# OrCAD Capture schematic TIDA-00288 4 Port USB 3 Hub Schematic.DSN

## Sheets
1 PAGE1_BLOCK_DIAGRAM: title: BLOCK DIAGRAM; rev: B
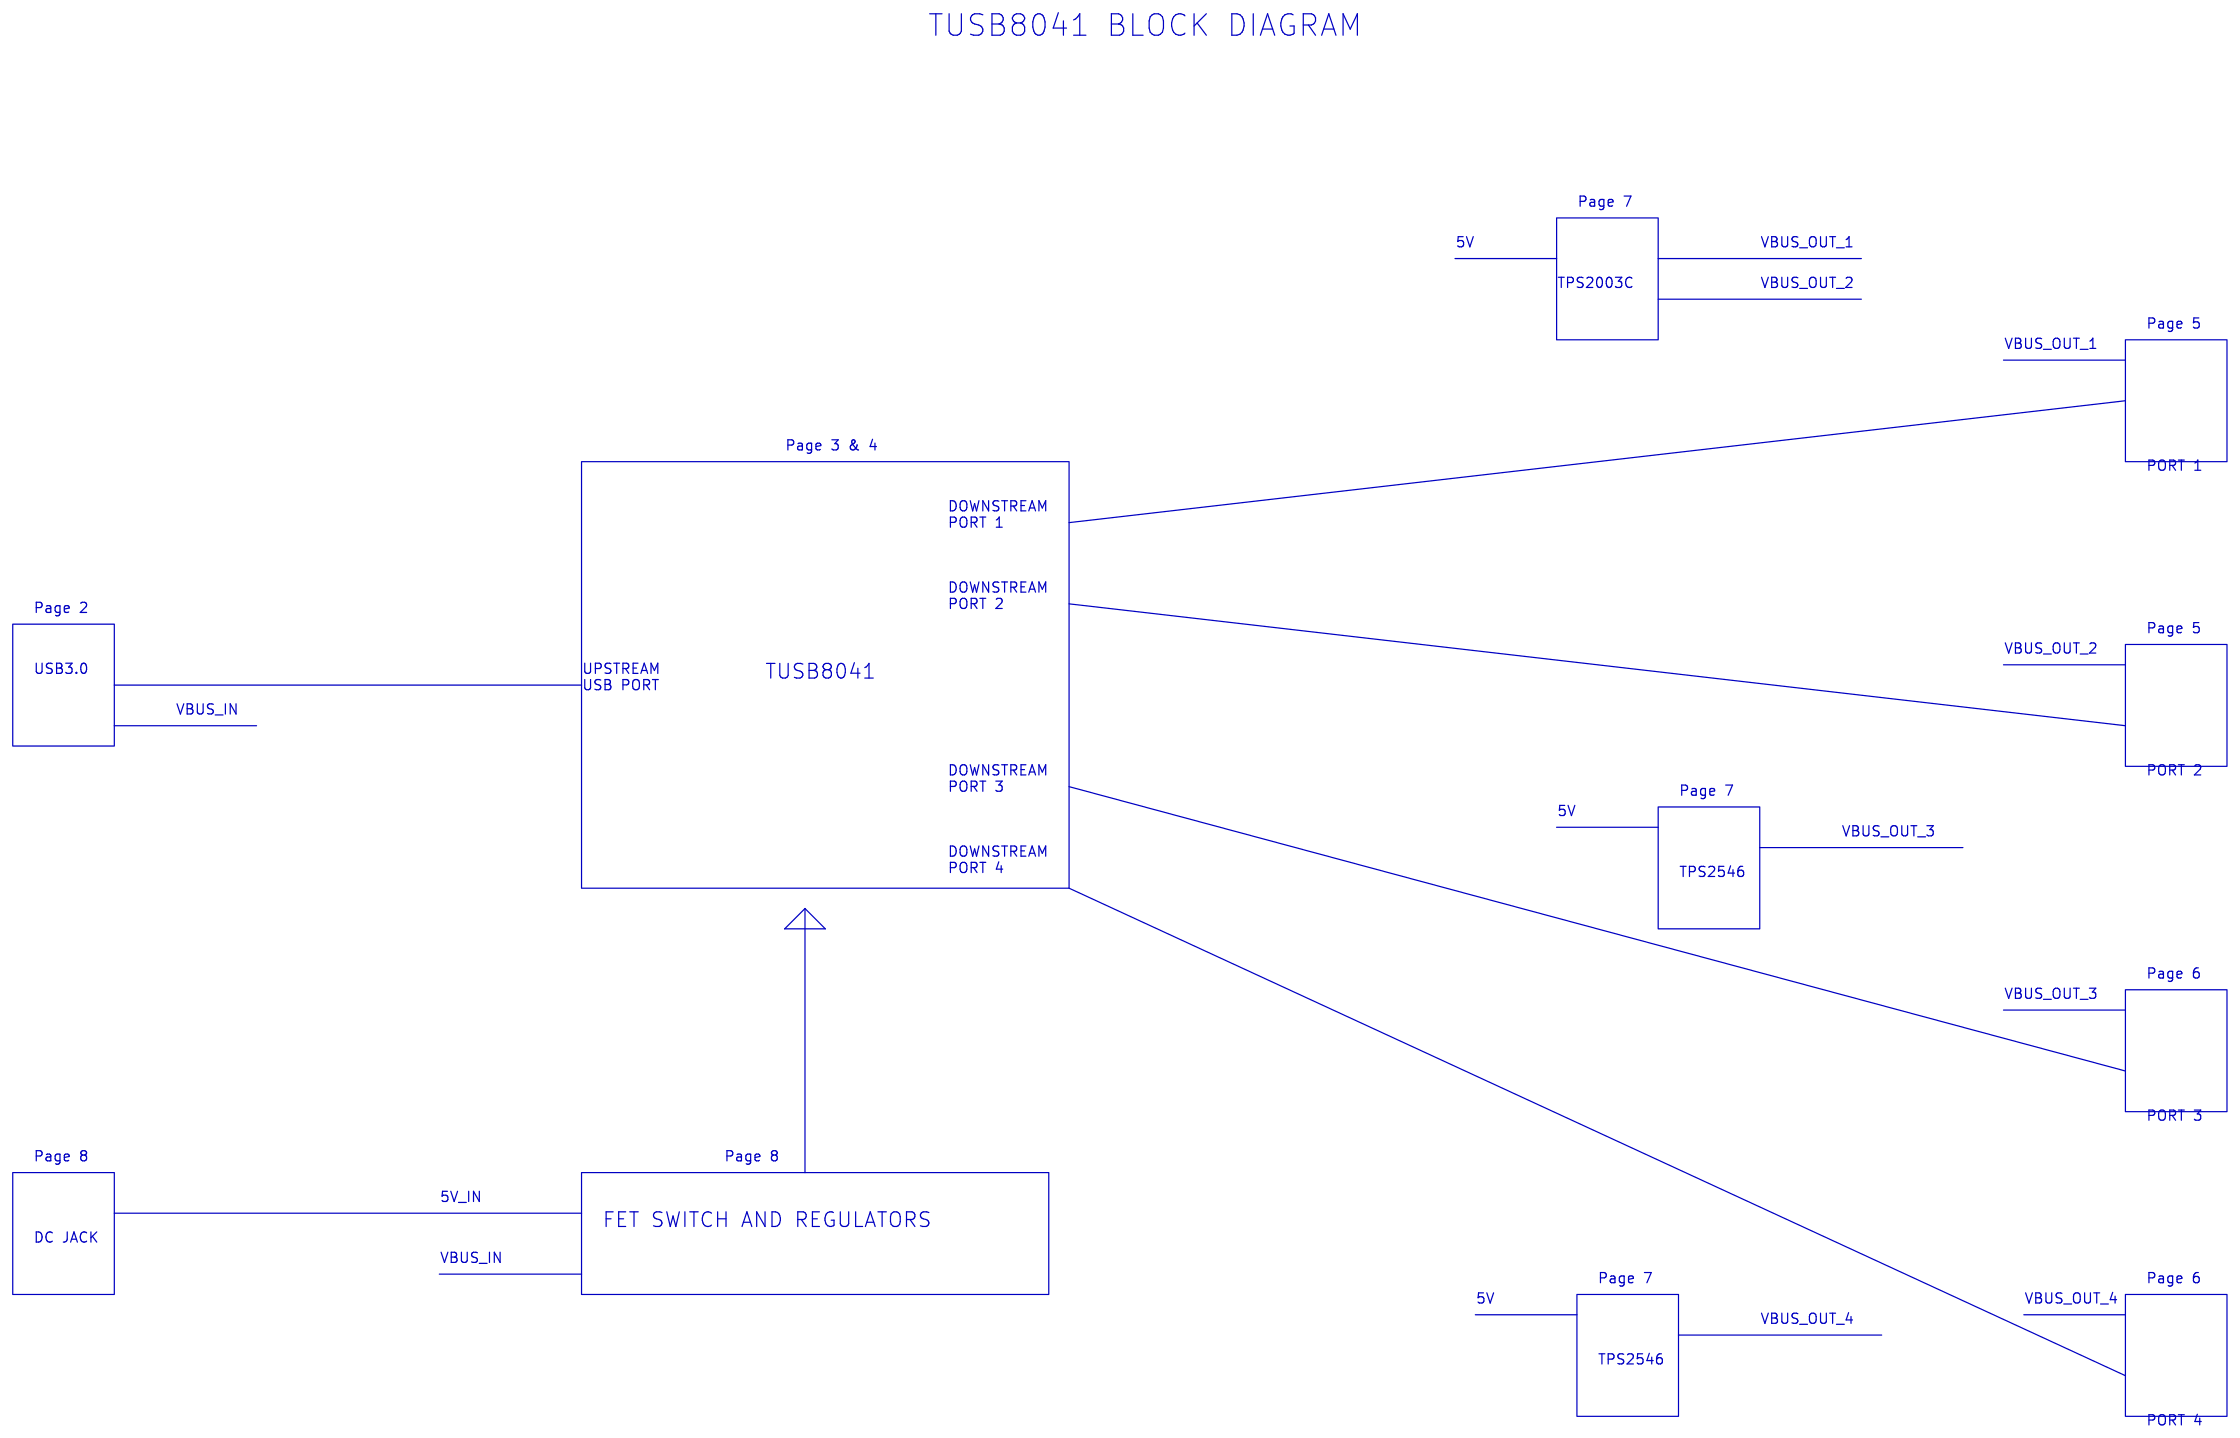
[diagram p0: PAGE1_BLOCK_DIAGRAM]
2 PAGE2_USB3_MICRO_B: size B; title: USB 3.0 MICRO-B CONNECTOR
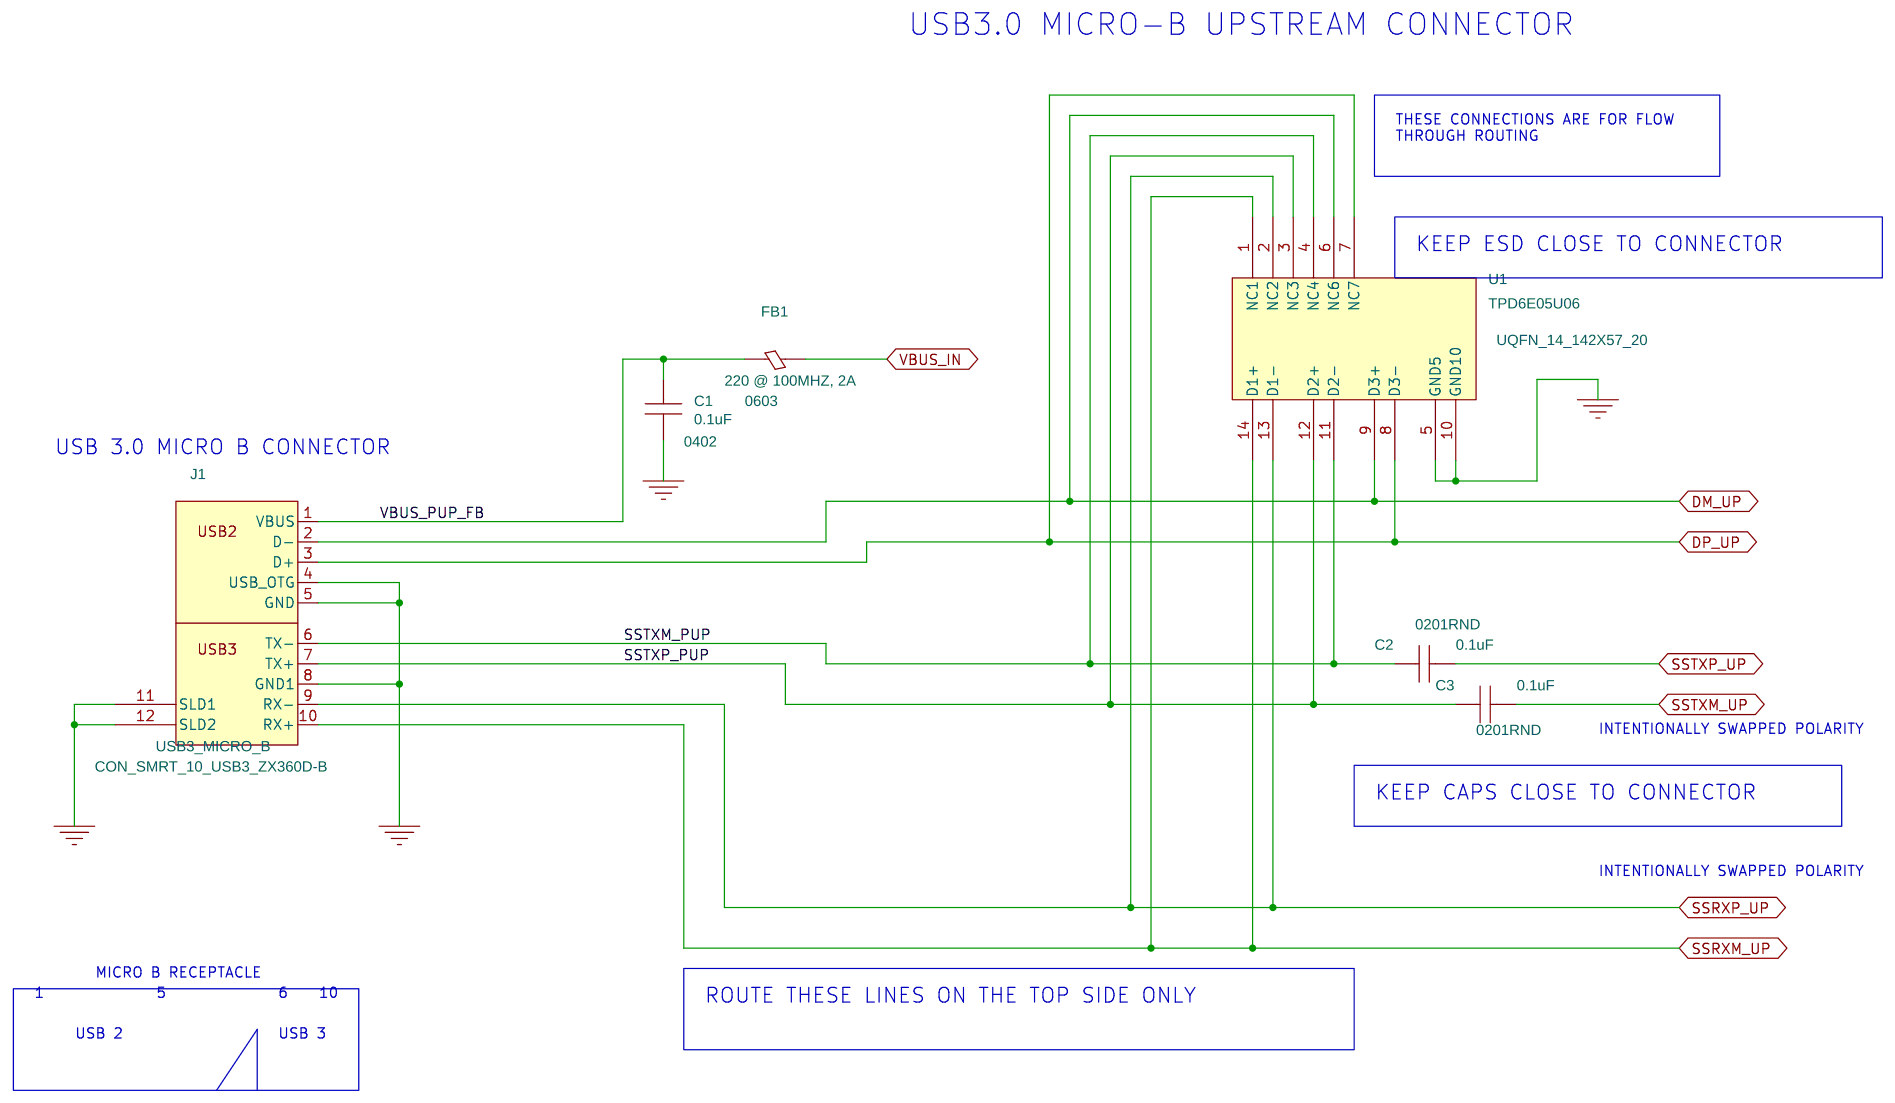
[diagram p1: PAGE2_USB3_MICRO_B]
3 PAGE3_TUSB8041: size B; title: TUSB8041 - PAGE 1
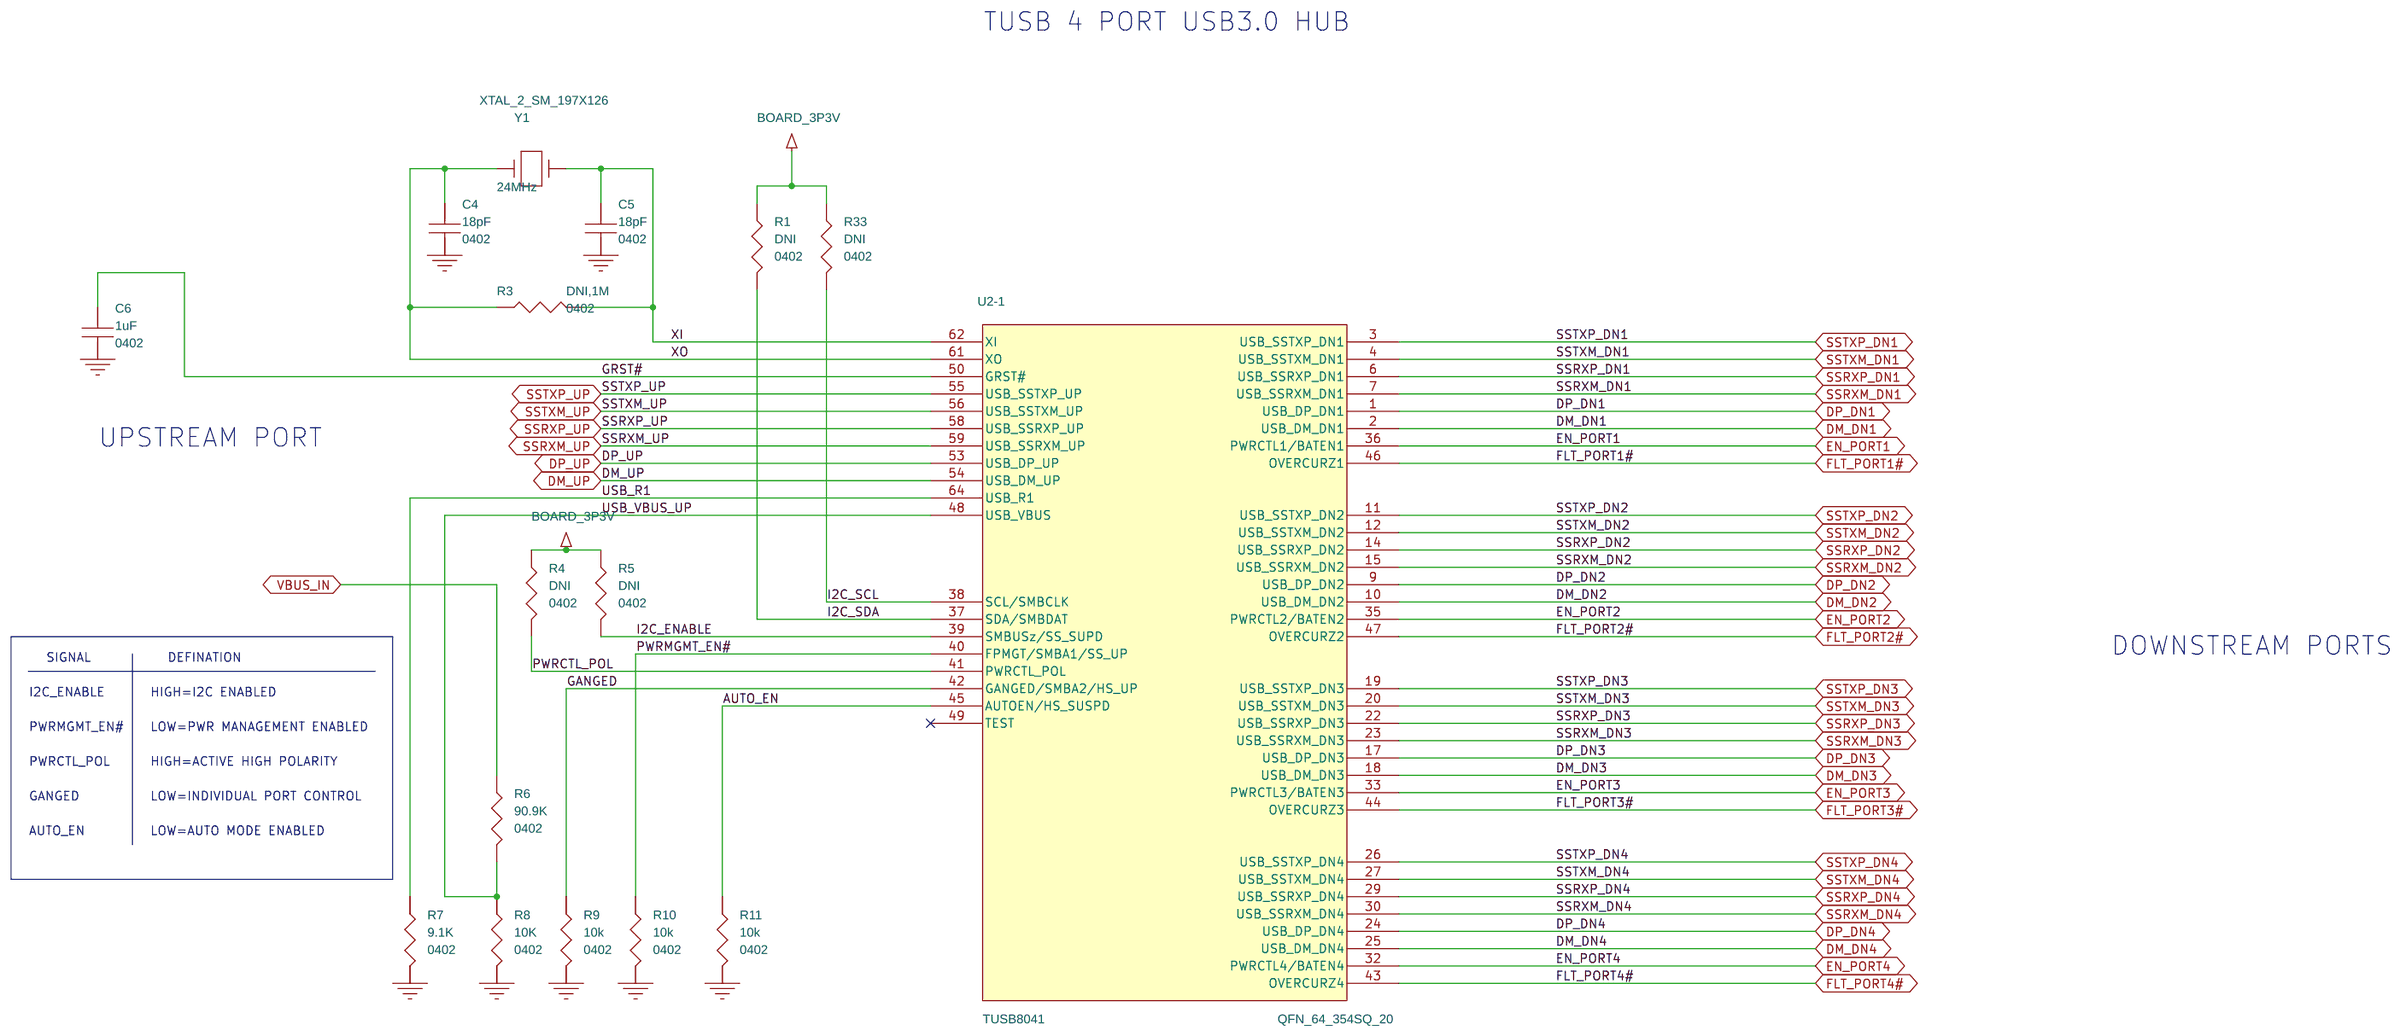
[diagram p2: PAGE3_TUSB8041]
4 PAGE4_TUSB8041_POWER: size B; title: TUSB POWER FOR HUB
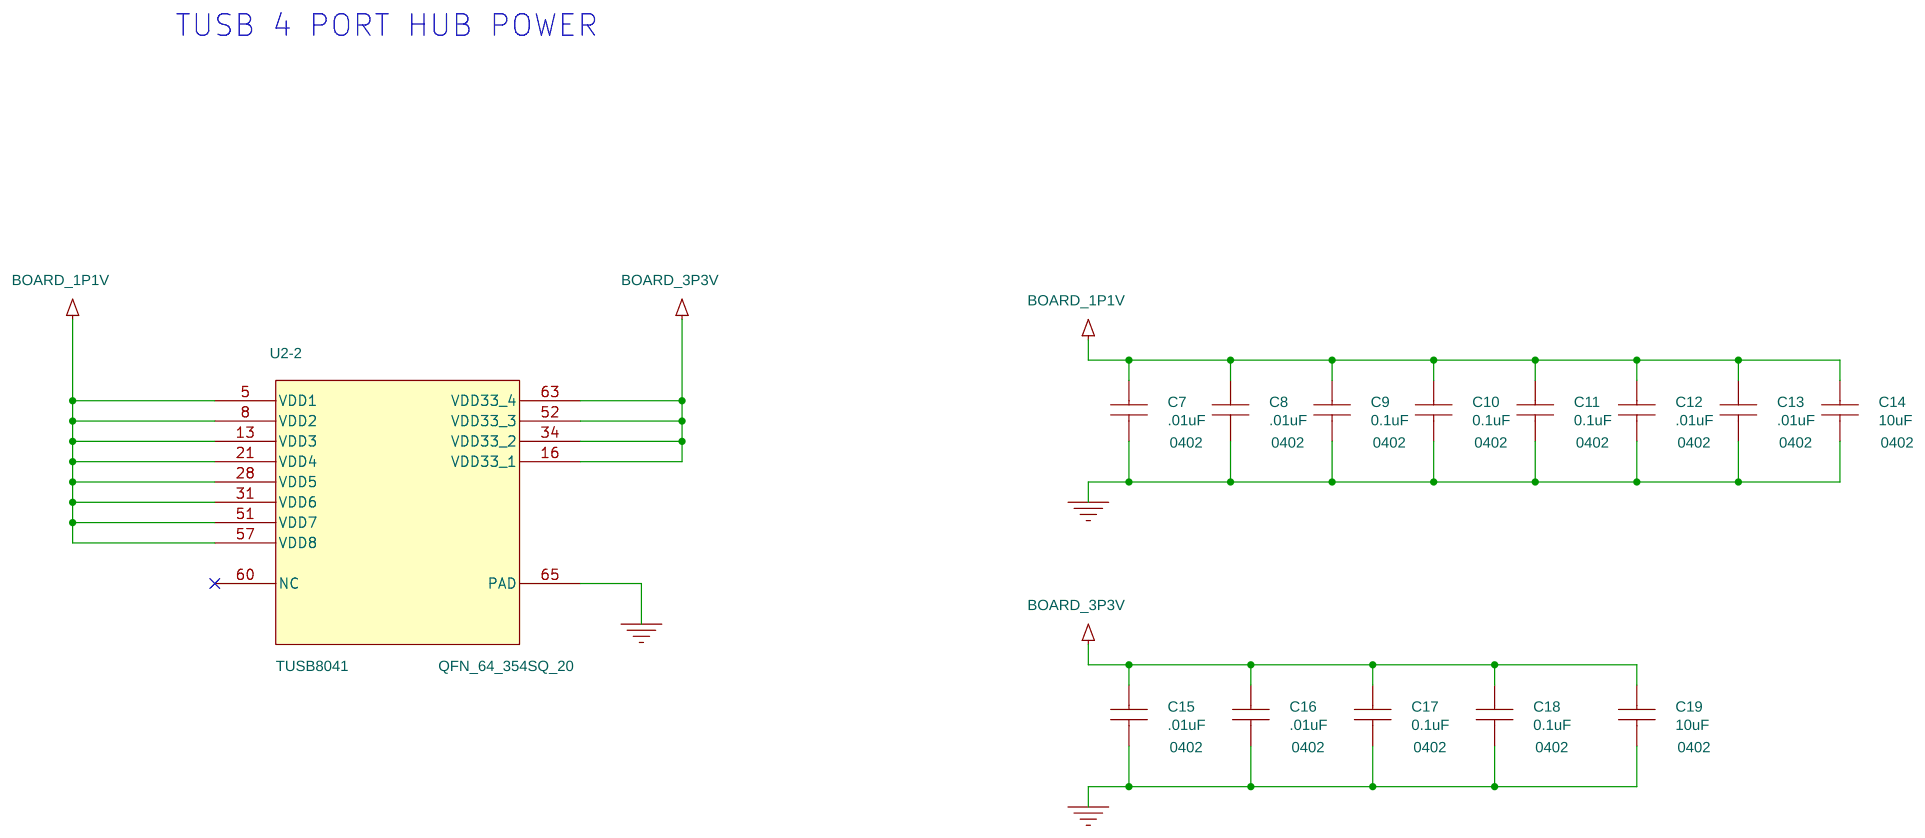
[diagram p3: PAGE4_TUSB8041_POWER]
5 PAGE5_USB_PORTS_1_2: size B; title: USB DOWNSTREAM PORTS 1 & 2
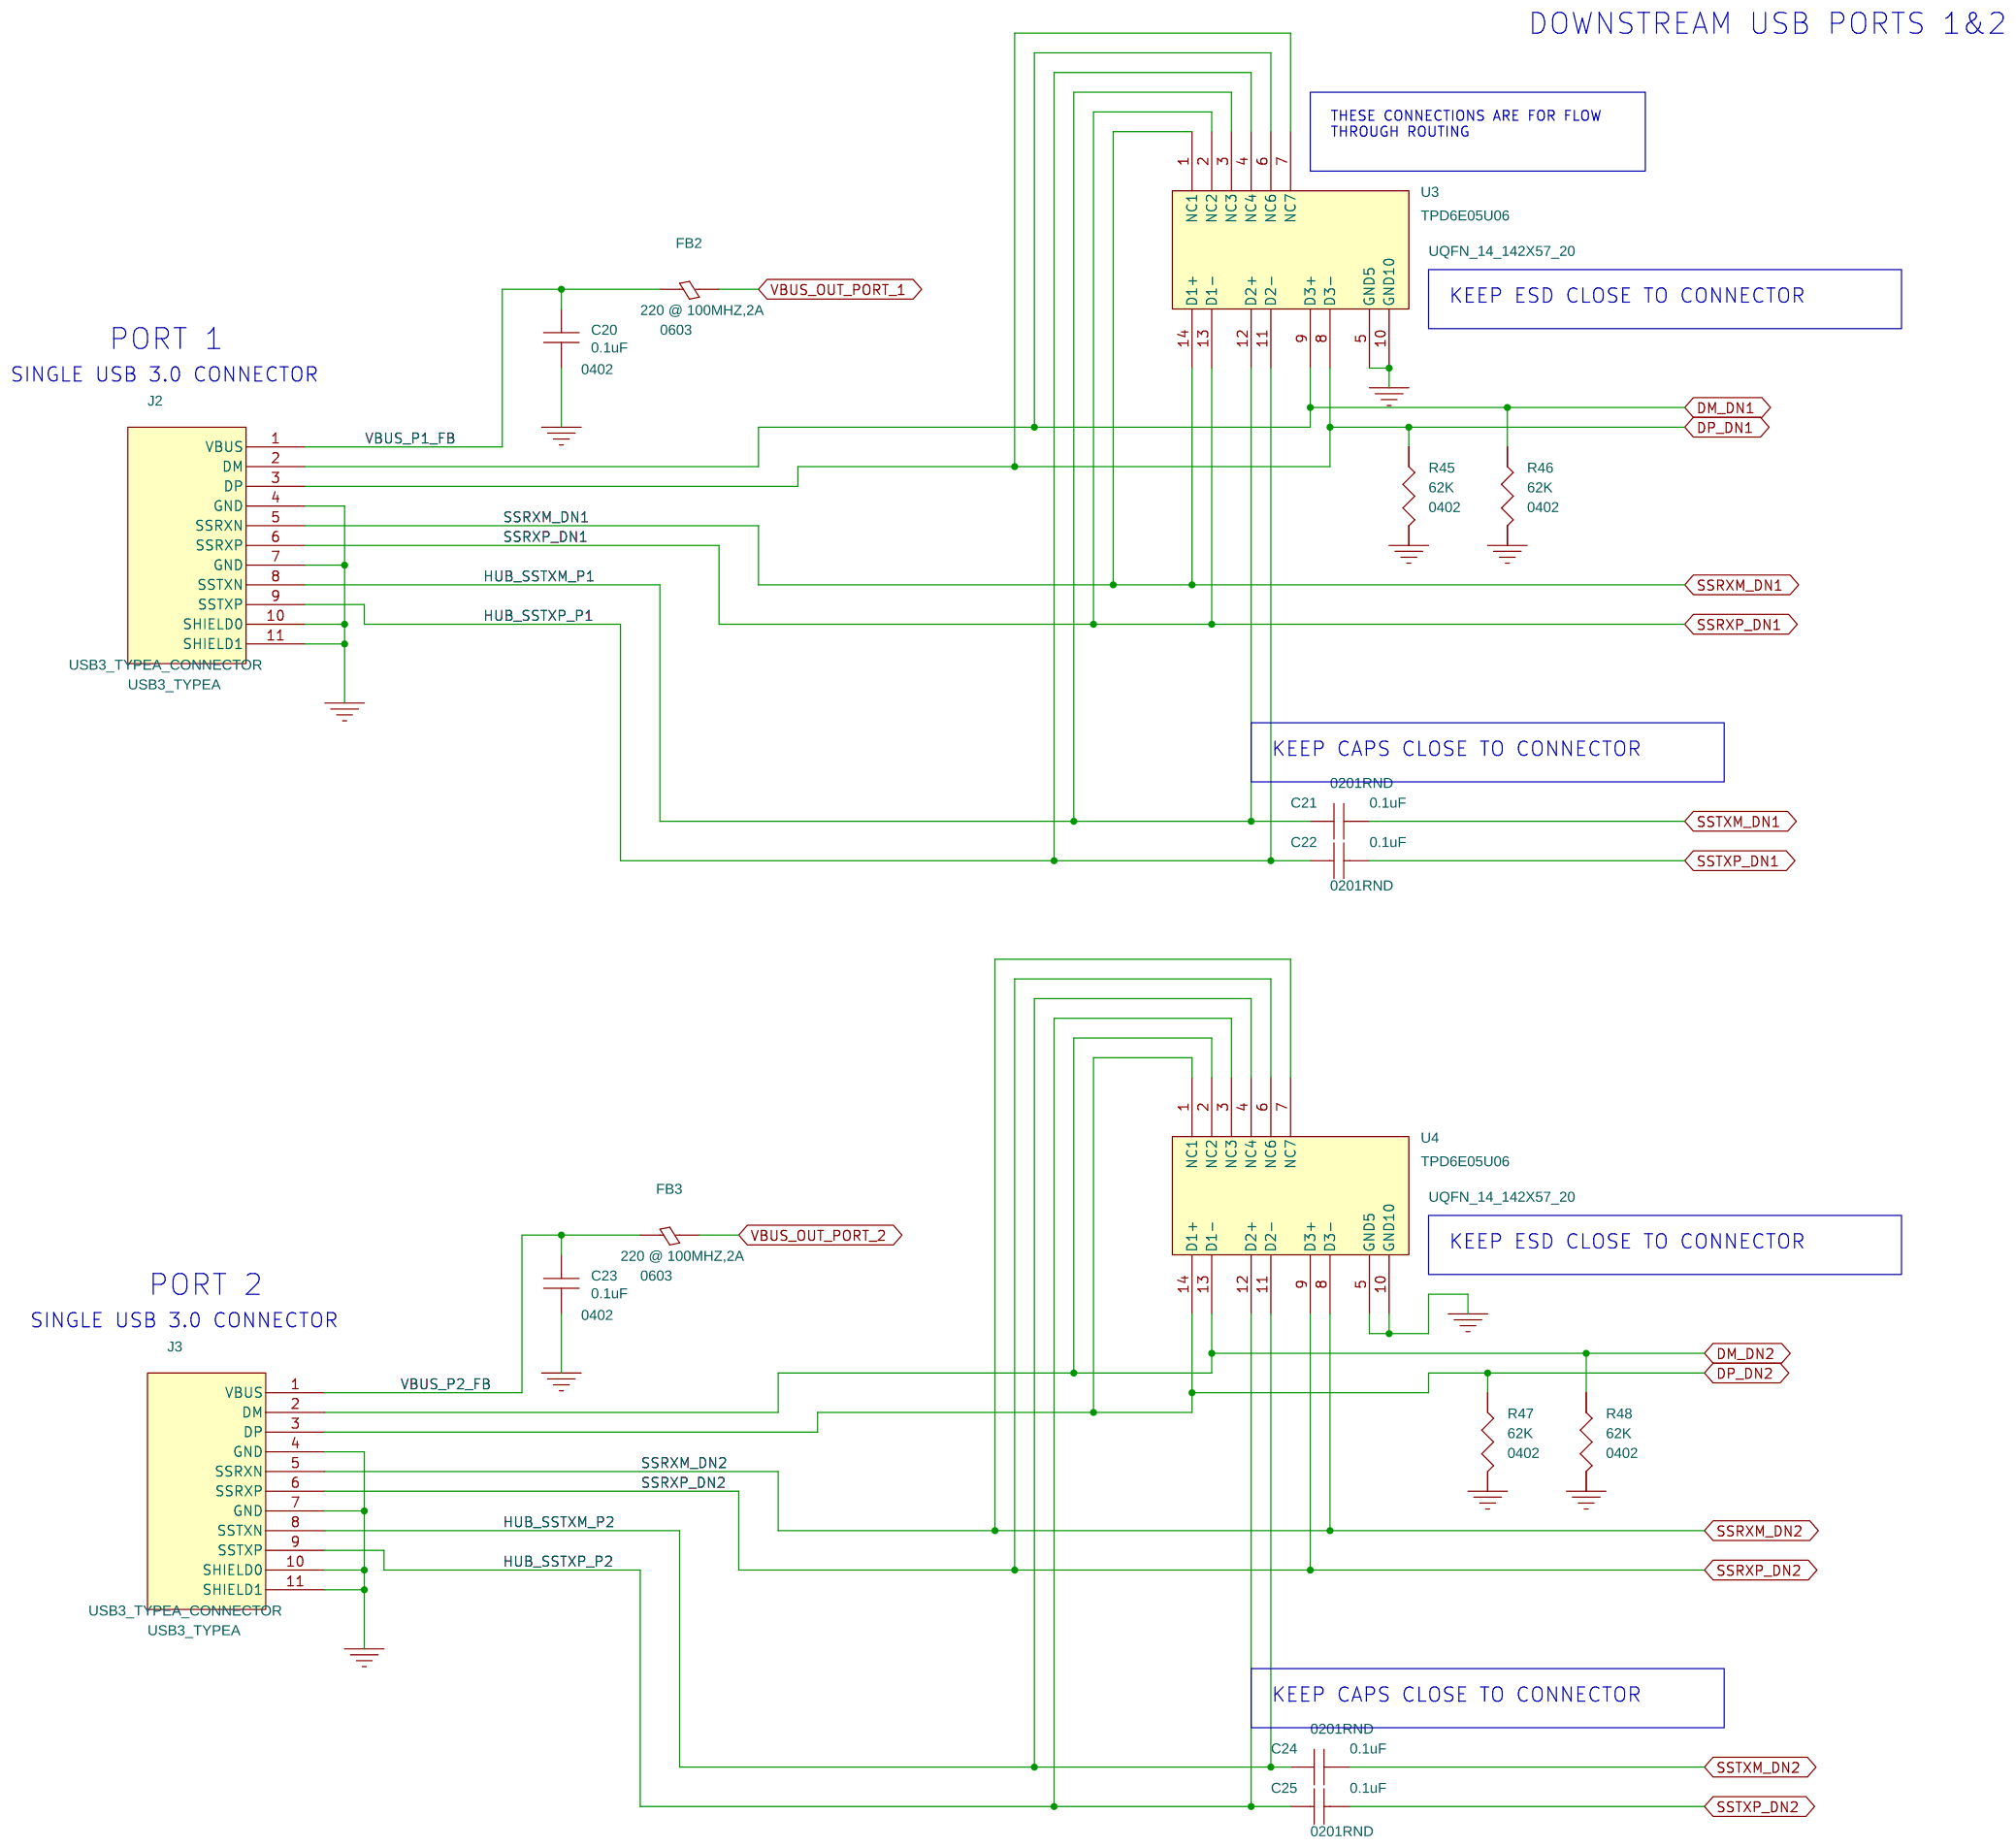
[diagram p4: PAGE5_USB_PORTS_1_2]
6 PAGE6_USB_PORTS_3_4: size B; title: USB DOWNSTREAM PORTS 3 & 4
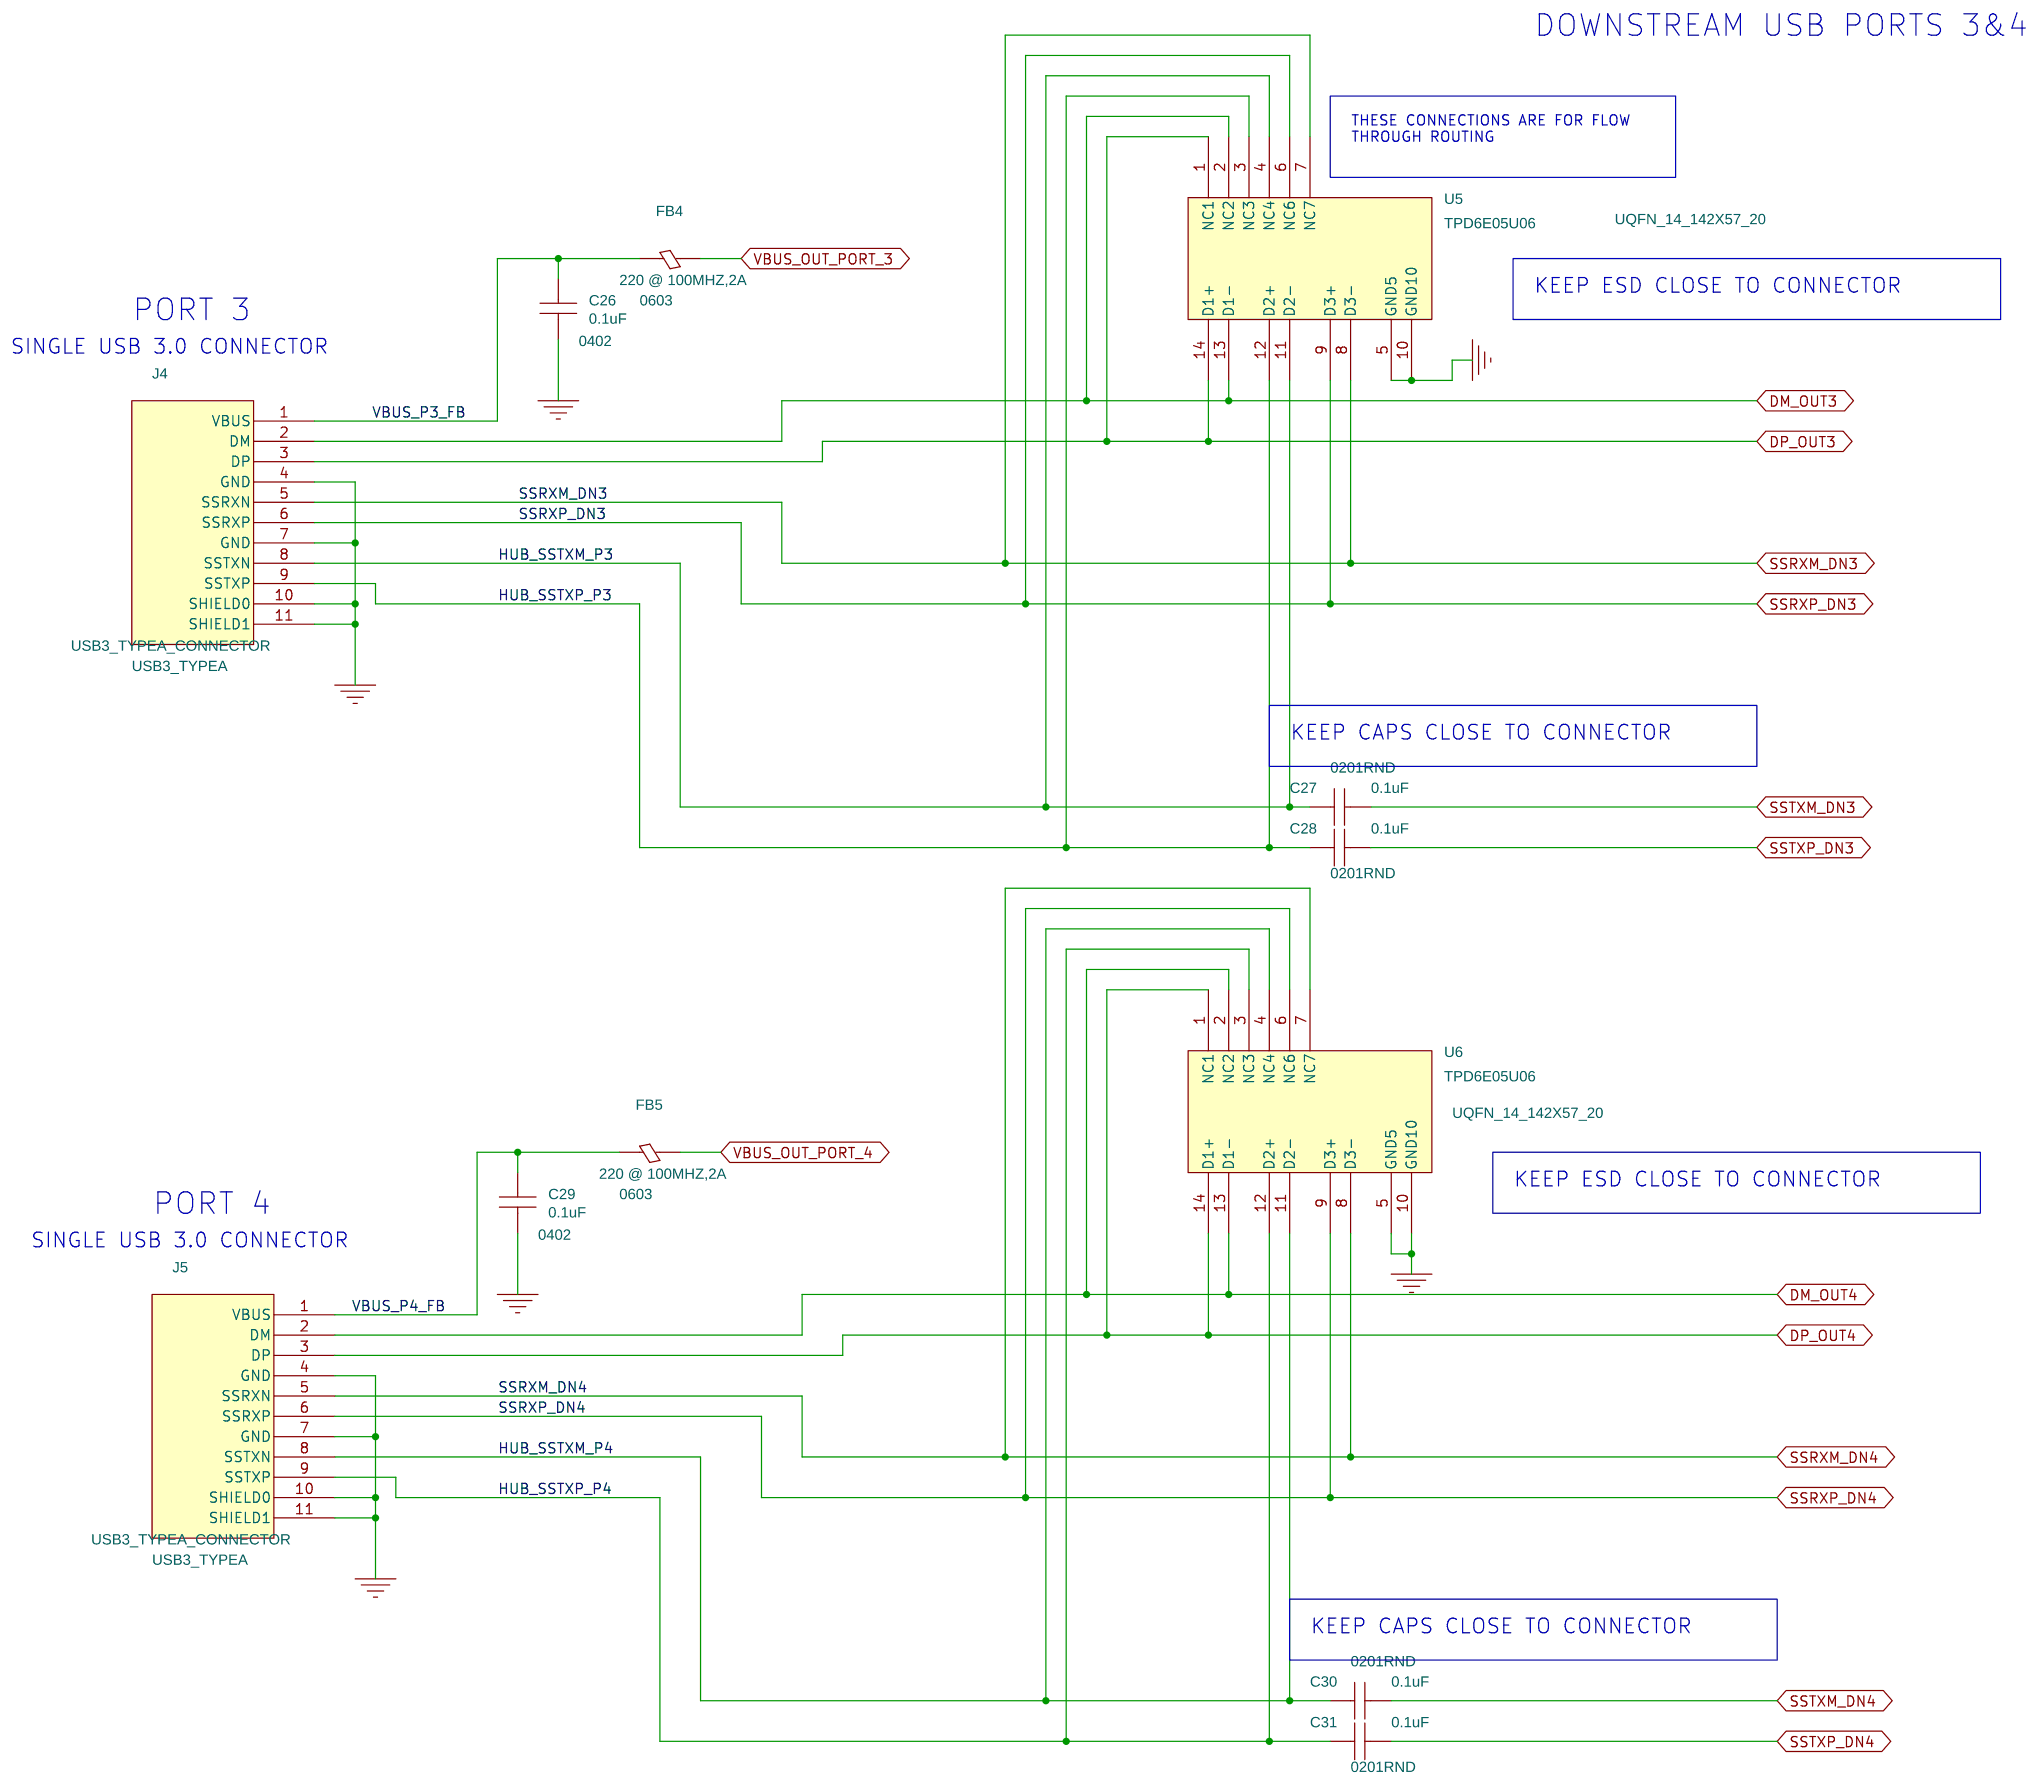
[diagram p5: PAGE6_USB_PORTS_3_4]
7 PAGE7_USB_POWER: size B; title: VBUS FOR USB PORTS
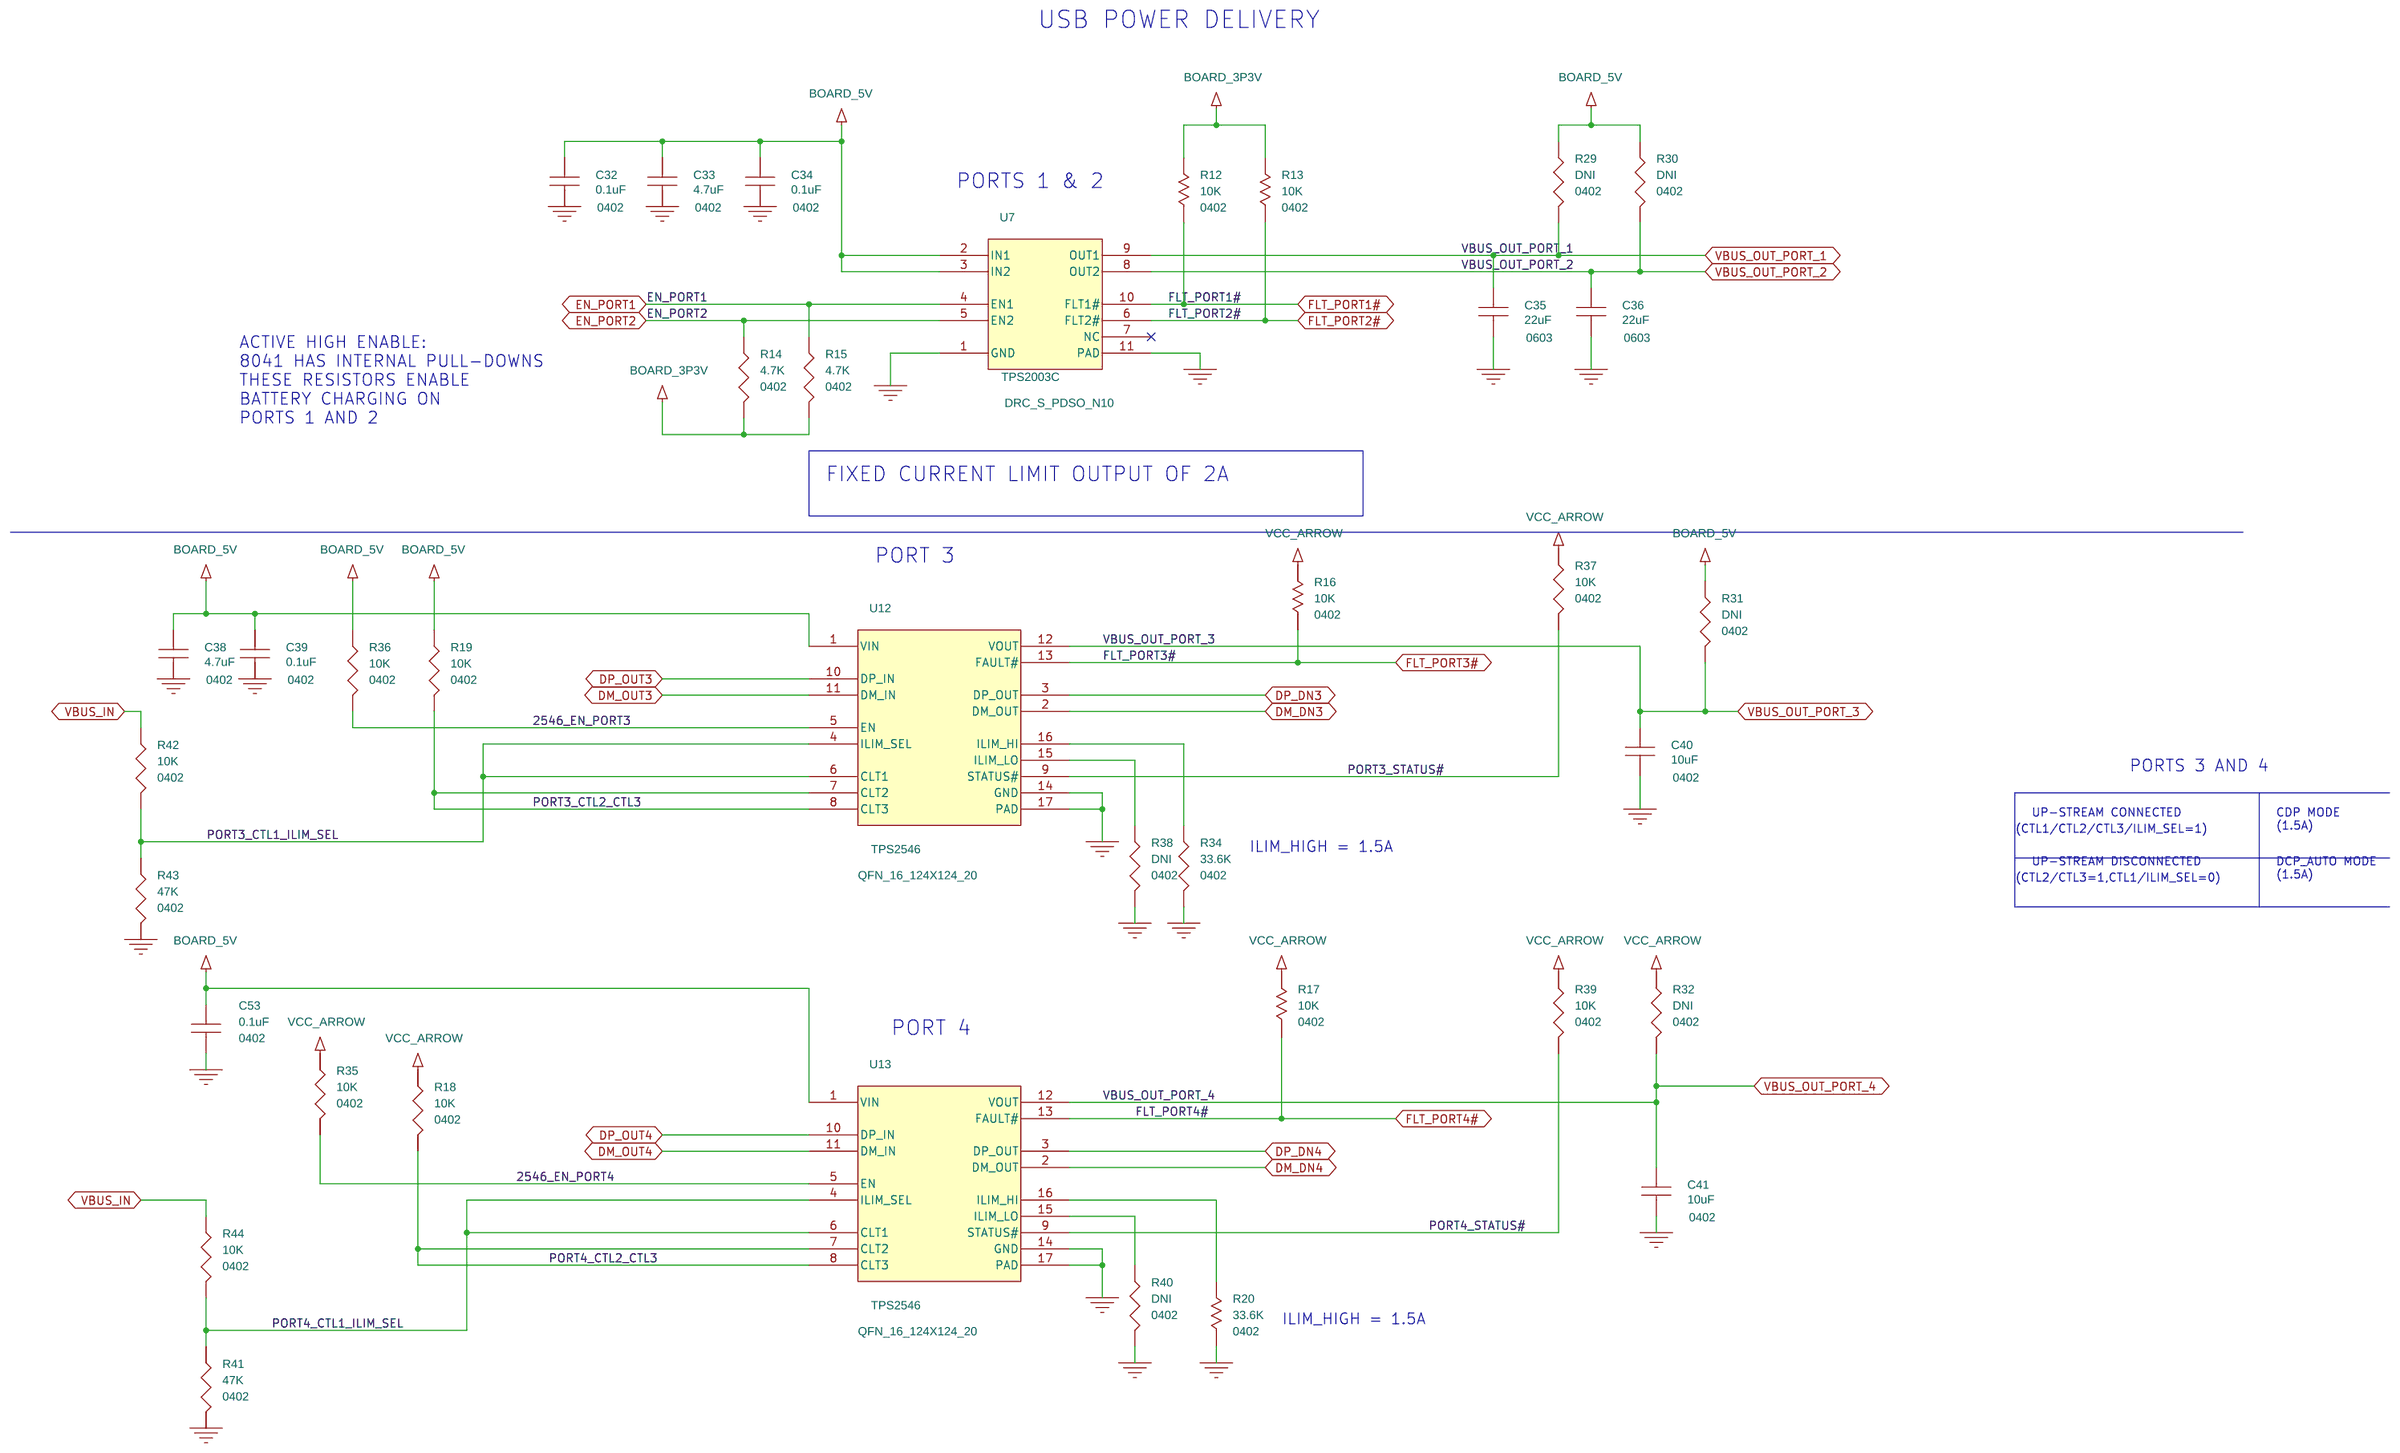
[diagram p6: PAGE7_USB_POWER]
8 PAGE8_POWER: size B; title: BOARD POWER
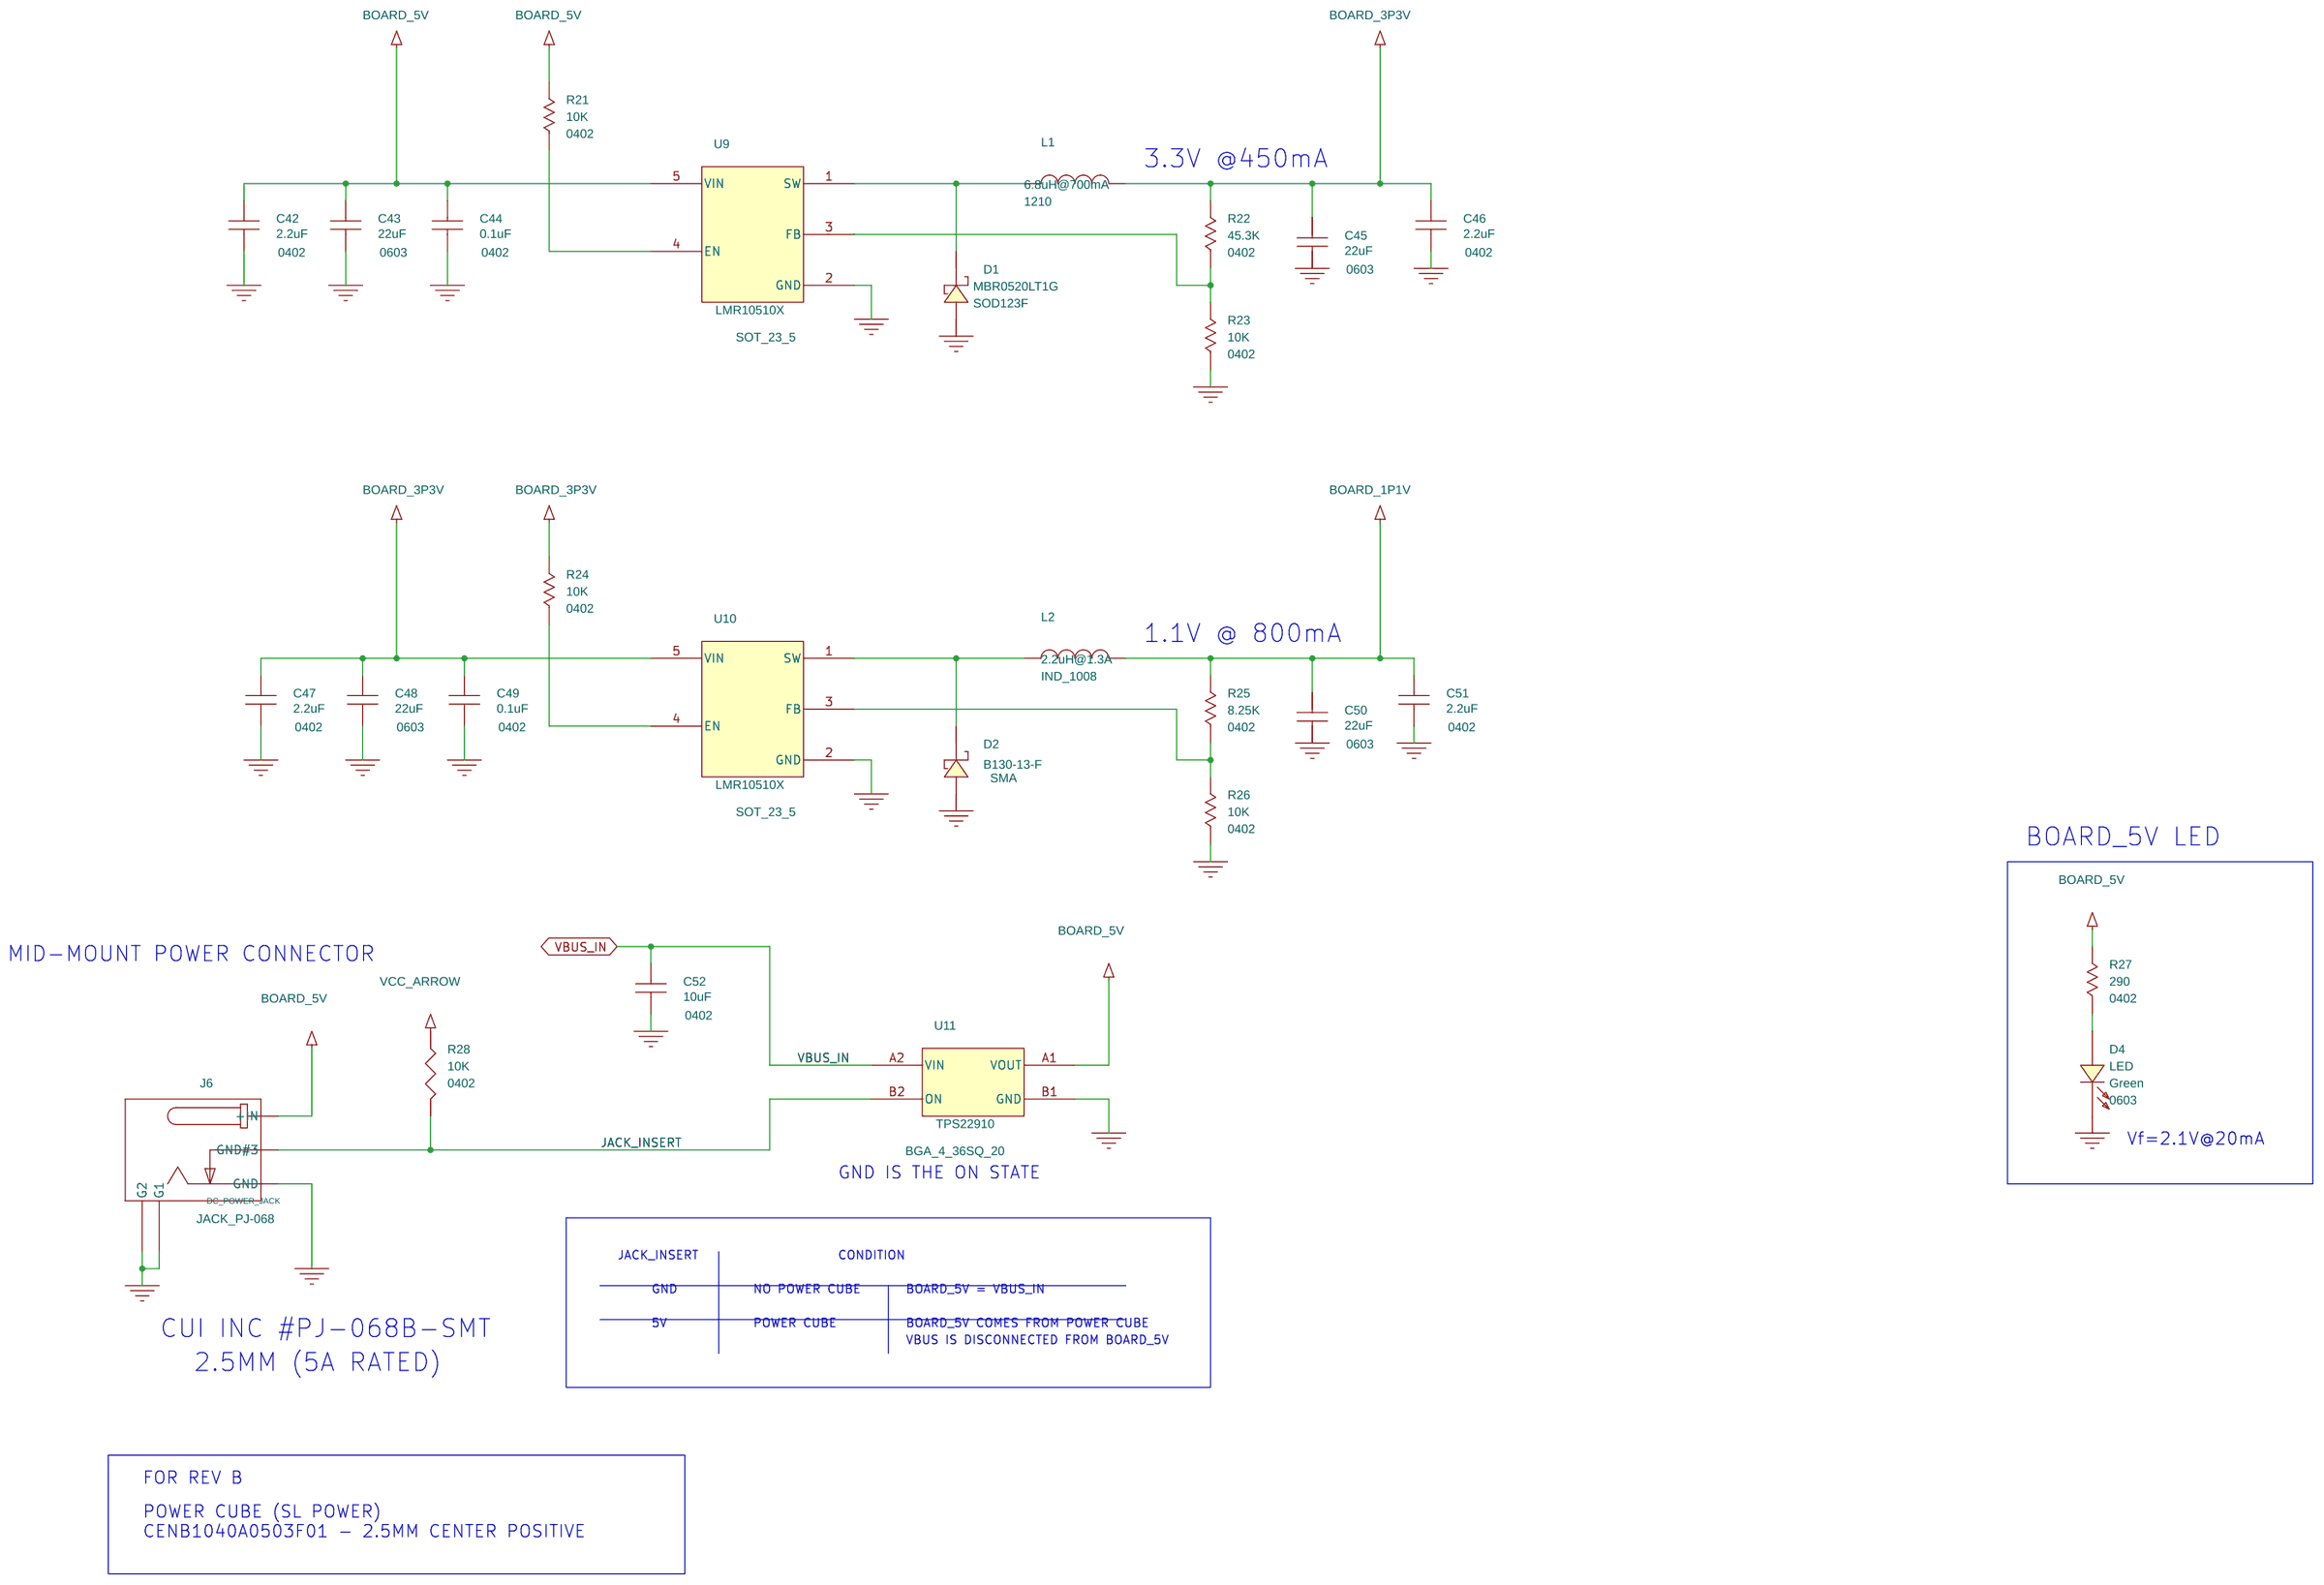
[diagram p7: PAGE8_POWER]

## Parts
sheet PAGE2_USB3_MICRO_B
C1  0.1uF  [0402]
C2  0.1uF  [0201RND]
C3  0.1uF  [0201RND]
FB1  220 @ 100MHZ, 2A  [0603]
J1  USB3_MICRO_B  [CON_SMRT_10_USB3_ZX360D-B]
U1  TPD6E05U06  [UQFN_14_142X57_20]
sheet PAGE3_TUSB8041
C4  18pF  [0402]
C5  18pF  [0402]
C6  1uF  [0402]
R1  DNI  [0402]
R3  DNI,1M  [0402]
R4  DNI  [0402]
R5  DNI  [0402]
R6  90.9K  [0402]
R7  9.1K  [0402]
R8  10K  [0402]
R9  10k  [0402]
R10  10k  [0402]
R11  10k  [0402]
R33  DNI  [0402]
U2  TUSB8041  [QFN_64_354SQ_20]  (sections -1,-2)
Y1  24MHz  [XTAL_2_SM_197X126]
sheet PAGE4_TUSB8041_POWER
C7  .01uF  [0402]
C8  .01uF  [0402]
C9  0.1uF  [0402]
C10  0.1uF  [0402]
C11  0.1uF  [0402]
C12  .01uF  [0402]
C13  .01uF  [0402]
C14  10uF  [0402]
C15  .01uF  [0402]
C16  .01uF  [0402]
C17  0.1uF  [0402]
C18  0.1uF  [0402]
C19  10uF  [0402]
sheet PAGE5_USB_PORTS_1_2
C20  0.1uF  [0402]
C21  0.1uF  [0201RND]
C22  0.1uF  [0201RND]
C23  0.1uF  [0402]
C24  0.1uF  [0201RND]
C25  0.1uF  [0201RND]
FB2  220 @ 100MHZ,2A  [0603]
FB3  220 @ 100MHZ,2A  [0603]
J2  USB3_TYPEA_CONNECTOR  [USB3_TYPEA]
J3  USB3_TYPEA_CONNECTOR  [USB3_TYPEA]
R45  62K  [0402]
R46  62K  [0402]
R47  62K  [0402]
R48  62K  [0402]
U3  TPD6E05U06  [UQFN_14_142X57_20]
U4  TPD6E05U06  [UQFN_14_142X57_20]
sheet PAGE6_USB_PORTS_3_4
C26  0.1uF  [0402]
C27  0.1uF  [0201RND]
C28  0.1uF  [0201RND]
C29  0.1uF  [0402]
C30  0.1uF  [0201RND]
C31  0.1uF  [0201RND]
FB4  220 @ 100MHZ,2A  [0603]
FB5  220 @ 100MHZ,2A  [0603]
J4  USB3_TYPEA_CONNECTOR  [USB3_TYPEA]
J5  USB3_TYPEA_CONNECTOR  [USB3_TYPEA]
U5  TPD6E05U06  [UQFN_14_142X57_20]
U6  TPD6E05U06  [UQFN_14_142X57_20]
sheet PAGE7_USB_POWER
C32  0.1uF  [0402]
C33  4.7uF  [0402]
C34  0.1uF  [0402]
C35  22uF  [0603]
C36  22uF  [0603]
C38  4.7uF  [0402]
C39  0.1uF  [0402]
C40  10uF  [0402]
C41  10uF  [0402]
C53  0.1uF  [0402]
R12  10K  [0402]
R13  10K  [0402]
R14  4.7K  [0402]
R15  4.7K  [0402]
R16  10K  [0402]
R17  10K  [0402]
R18  10K  [0402]
R19  10K  [0402]
R20  33.6K  [0402]
R29  DNI  [0402]
R30  DNI  [0402]
R31  DNI  [0402]
R32  DNI  [0402]
R34  33.6K  [0402]
R35  10K  [0402]
R36  10K  [0402]
R37  10K  [0402]
R38  DNI  [0402]
R39  10K  [0402]
R40  DNI  [0402]
R41  47K  [0402]
R42  10K  [0402]
R43  47K  [0402]
R44  10K  [0402]
U7  TPS2003C  [DRC_S_PDSO_N10]
U12  TPS2546  [QFN_16_124X124_20]
U13  TPS2546  [QFN_16_124X124_20]
sheet PAGE8_POWER
C42  2.2uF  [0402]
C43  22uF  [0603]
C44  0.1uF  [0402]
C45  22uF  [0603]
C46  2.2uF  [0402]
C47  2.2uF  [0402]
C48  22uF  [0603]
C49  0.1uF  [0402]
C50  22uF  [0603]
C51  2.2uF  [0402]
C52  10uF  [0402]
D1  MBR0520LT1G  [SOD123F]
D2  B130-13-F  [SMA]
D4  LED  [0603]
J6  DC_PWR_JACK  [JACK_PJ-068]
L1  6.8uH@700mA  [1210]
L2  2.2uH@1.3A  [IND_1008]
R21  10K  [0402]
R22  45.3K  [0402]
R23  10K  [0402]
R24  10K  [0402]
R25  8.25K  [0402]
R26  10K  [0402]
R27  290  [0402]
R28  10K  [0402]
U9  LMR10510X  [SOT_23_5]
U10  LMR10510X  [SOT_23_5]
U11  TPS22910  [BGA_4_36SQ_20]

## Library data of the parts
C1-C6 C20-C31 = CAP_NP: 6.3V Capacitor
FB1-FB5 = FERRITE_BEAD: Ferrite Bead; Digi-Key Part Number: 490-3992-1-ND; Manufacturer: MuRata; Manufacturer's Part Number: BLM18EG221SN1D
J1 = USB3_MICRO_B: MANUFACTURER: HIROSE ELECTRIC; MANUFACTURER'S PART NUMBER: ZX360D-B-10P
U1 U3-U6 = TPD6E05U06: MANUFACTURER: TEXAS INSTRUMENTS
R1 R4-R11 R14 R15 R18 R19 R28-R48 = R
R3 = R: Resistor
U2 = TUSB8041: MANUFACTURER: TEXAS INSTRUMENTS; Color: Default; Location X-Coordinate: 0; Location Y-Coordinate: 0; Package Type: Heterogeneous; Power Pins Visible: False; Primitive: DEFAULT; SPLIT_INST: TRUE; SWAP_INFO: (S1+S2)
Y1 = CRYSTAL: Crystal; Manufacturer: CTS Freq Controls; Manufacturer's Part Number: 445C25D24M00000
C7-C19 C32-C36 C38-C53 = CAP_NP
J2-J5 = USB3_TYPEA_CONNECTER: USB3 Type A Connector; Manufacturer: FCI; Manufacturer's Part Number: 10117835-002LF; TI_Silktext: USB3_DS2
R12 R13 R16 R17 R20-R27 = R_v2
U7 = TPS2003C: MANUFACTURER: TEXAS INSTRUMENTS; MANUFACTURER'S PART NUMBER: TPS2003CDRC
U12 U13 = TPS2546
D1 = DIODE_SCHOTTKY: Manufacturer: ON Semiconductor
D2 = DIODE_SCHOTTKY: Manufacturer: DIODES Inc
D4 = LED: LED Color: Green; Manufacturer: Lite-On Inc.; Manufacturer's Part Number: LTST-C171GKT
J6 = 6140046600_DC_PWR_JACK_0: $SEC: 1; CDS_LIB: connector; DEVICE_NAME: DC_POWER_JACK; DRAWING: @LIGHTNING_BOLT_NB_LIB.NOTE_BOOK(SCH_1):PAGE2; GroupName: COMMON; Manufacturer: CUI Inc.; Manufacturer Part Number: PJ-068B-SMT; Manufacturer's Part Number: PJ-068B-SMT; PHYS_PAGE: 2; ROT: 0; VER: 1; XY: (-4550,4450)
L1 = INDUCTOR: Manufacturer: TDK; Manufacturer's Part Number: NLCV32T6R8MPFR
L2 = INDUCTOR: Manufacturer: Murata; Manufacturer's Part Number: LQM2HPN2R2MG0L
U9 U10 = LMR10510X: MANUFACTURER: TEXAS INSTRUMENTS; MANUFACTURER'S PART NUMBER: LMR10510XMF
U11 = TPS22910: MANUFACTURER: TEXAS INSTRUMENTS; MANUFACTURER'S PART NUMBER: TPS22910AYZVR

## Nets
GND: C1.2 C4.2 C5.2 C6.2 C7.2 C8.2 C9.2 C10.2 C11.2 C12.2 C13.2 C14.2 C15.2 C16.2 C17.2 C18.2 C19.2 C20.2 C23.2 C26.2 C29.2 C32.2 C33.2 C34.2 C35.2 C36.2 C38.2 C39.2 C40.2 C41.2 C42.2 C43.2 C44.2 C45.2 C46.2 C47.2 C48.2 C49.2 C50.2 C51.2 C52.2 C53.2 D1.1(ANODE) D2.1(ANODE) D4.1(CATHODE) J1.4(USB_OTG) J1.5(GND) J1.8(GND1) J1.11(SLD1) J1.12(SLD2) J2.4(GND) J2.7(GND) J2.10(SHIELD0) J2.11(SHIELD1) J3.4(GND) J3.7(GND) J3.10(SHIELD0) J3.11(SHIELD1) J4.4(GND) J4.7(GND) J4.10(SHIELD0) J4.11(SHIELD1) J5.4(GND) J5.7(GND) J5.10(SHIELD0) J5.11(SHIELD1) J6.2(GND) J6.4(G1) J6.5(G2) R7.2 R8.2 R9.2 R10.2 R11.2 R20.2 R23.2 R26.2 R34.2 R38.2 R40.2 R41.2 R43.2 R45.2 R46.2 R47.2 R48.2 U1.5(GND5) U1.10(GND10) U2.65(PAD) U3.5(GND5) U3.10(GND10) U4.5(GND5) U4.10(GND10) U5.5(GND5) U5.10(GND10) U6.5(GND5) U6.10(GND10) U7.1(GND) U7.11(PAD) U9.2(GND) U10.2(GND) U11.B1(GND) U12.14(GND) U12.17(PAD) U13.14(GND) U13.17(PAD)
VBUS_IN: C52.1 FB1.2 R6.1 R42.1 R44.1 U11.A2(VIN)
VBUS_OUT_PORT_1: C35.1 FB2.2 R29.2 U7.9(OUT1)
VBUS_OUT_PORT_2: C36.1 FB3.2 R30.2 U7.8(OUT2)
VBUS_OUT_PORT_3: C40.1 FB4.2 R31.2 U12.12(VOUT)
VBUS_OUT_PORT_4: C41.1 FB5.2 R32.2 U13.12(VOUT)
VBUS_P1_FB: C20.1 FB2.1 J2.1(VBUS)
VBUS_P2_FB: C23.1 FB3.1 J3.1(VBUS)
VBUS_P3_FB: C26.1 FB4.1 J4.1(VBUS)
VBUS_P4_FB: C29.1 FB5.1 J5.1(VBUS)
VBUS_PUP_FB: C1.1 FB1.1 J1.1(VBUS)
2546_EN_PORT3: R36.2 U12.5(EN)
2546_EN_PORT4: R35.2 U13.5(EN)
AUTO_EN: R11.1 U2.45(AUTOEN/HS_SUSPD)
BOARD_1P1V: C7.1 C8.1 C9.1 C10.1 C11.1 C12.1 C13.1 C14.1 C50.1 C51.1 L2.2 R25.1 U2.5(VDD1) U2.8(VDD2) U2.13(VDD3) U2.21(VDD4) U2.28(VDD5) U2.31(VDD6) U2.51(VDD7) U2.57(VDD8)
BOARD_3P3V: C15.1 C16.1 C17.1 C18.1 C19.1 C45.1 C46.1 C47.1 C48.1 C49.1 L1.2 R1.1 R4.1 R5.1 R12.1 R13.1 R14.2 R15.2 R16.1 R17.1 R22.1 R24.1 R33.1 U2.16(VDD33_1) U2.34(VDD33_2) U2.52(VDD33_3) U2.63(VDD33_4) U10.5(VIN)
BOARD_5V: C32.1 C33.1 C34.1 C38.1 C39.1 C42.1 C43.1 C44.1 C53.1 J6.1(+IN) R18.1 R19.1 R21.1 R27.1 R28.1 R29.1 R30.1 R31.1 R32.1 R35.1 R36.1 R37.1 R39.1 U7.2(IN1) U7.3(IN2) U9.5(VIN) U11.A1(VOUT) U12.1(VIN) U13.1(VIN)
DM_DN1: J2.2(DM) R46.1 U2.2(USB_DM_DN1) U3.6(NC6) U3.9(D3+)
DM_DN2: J3.2(DM) R48.1 U2.10(USB_DM_DN2) U4.2(NC2) U4.13(D1-)
DM_DN3: U2.18(USB_DM_DN3) U12.2(DM_OUT)
DM_DN4: U2.25(USB_DM_DN4) U13.2(DM_OUT)
DM_OUT3: J4.2(DM) U5.2(NC2) U5.13(D1-) U12.11(DM_IN)
DM_OUT4: J5.2(DM) U6.2(NC2) U6.13(D1-) U13.11(DM_IN)
DM_UP: J1.2(D-) U1.6(NC6) U1.9(D3+) U2.54(USB_DM_UP)
DP_DN1: J2.3(DP) R45.1 U2.1(USB_DP_DN1) U3.7(NC7) U3.8(D3-)
DP_DN2: J3.3(DP) R47.1 U2.9(USB_DP_DN2) U4.1(NC1) U4.14(D1+)
DP_DN3: U2.17(USB_DP_DN3) U12.3(DP_OUT)
DP_DN4: U2.24(USB_DP_DN4) U13.3(DP_OUT)
DP_OUT3: J4.3(DP) U5.1(NC1) U5.14(D1+) U12.10(DP_IN)
DP_OUT4: J5.3(DP) U6.1(NC1) U6.14(D1+) U13.10(DP_IN)
DP_UP: J1.3(D+) U1.7(NC7) U1.8(D3-) U2.53(USB_DP_UP)
EN_PORT1: R15.1 U2.36(PWRCTL1/BATEN1) U7.4(EN1)
EN_PORT2: R14.1 U2.35(PWRCTL2/BATEN2) U7.5(EN2)
EN_PORT3: U2.33(PWRCTL3/BATEN3)
EN_PORT4: U2.32(PWRCTL4/BATEN4)
FLT_PORT1#: R12.2 U2.46(OVERCURZ1) U7.10(FLT1#)
FLT_PORT2#: R13.2 U2.47(OVERCURZ2) U7.6(FLT2#)
FLT_PORT3#: R16.2 U2.44(OVERCURZ3) U12.13(FAULT#)
FLT_PORT4#: R17.2 U2.43(OVERCURZ4) U13.13(FAULT#)
GANGED: R9.1 U2.42(GANGED/SMBA2/HS_UP)
GRST#: C6.1 U2.50(GRST#)
HUB_SSTXM_P1: C21.1 J2.8(SSTXN) U3.3(NC3) U3.12(D2+)
HUB_SSTXM_P2: C24.1 J3.8(SSTXN) U4.4(NC4) U4.11(D2-)
HUB_SSTXM_P3: C27.1 J4.8(SSTXN) U5.4(NC4) U5.11(D2-)
HUB_SSTXM_P4: C30.1 J5.8(SSTXN) U6.4(NC4) U6.11(D2-)
HUB_SSTXP_P1: C22.1 J2.9(SSTXP) U3.4(NC4) U3.11(D2-)
HUB_SSTXP_P2: C25.1 J3.9(SSTXP) U4.3(NC3) U4.12(D2+)
HUB_SSTXP_P3: C28.1 J4.9(SSTXP) U5.3(NC3) U5.12(D2+)
HUB_SSTXP_P4: C31.1 J5.9(SSTXP) U6.3(NC3) U6.12(D2+)
I2C_ENABLE: R5.2 U2.39(SMBUSz/SS_SUPD)
I2C_SCL: R33.2 U2.38(SCL/SMBCLK)
I2C_SDA: R1.2 U2.37(SDA/SMBDAT)
JACK_INSERT: J6.3(GND#3) R28.2 U11.B2(ON)
PORT3_CTL1_ILIM_SEL: R42.2 R43.1 U12.4(ILIM_SEL) U12.6(CLT1)
PORT3_CTL2_CTL3: R19.2 U12.7(CLT2) U12.8(CLT3)
PORT3_STATUS#: R37.2 U12.9(STATUS#)
PORT4_CTL1_ILIM_SEL: R41.1 R44.2 U13.4(ILIM_SEL) U13.6(CLT1)
PORT4_CTL2_CTL3: R18.2 U13.7(CLT2) U13.8(CLT3)
PORT4_STATUS#: R39.2 U13.9(STATUS#)
PWRCTL_POL: R4.2 U2.41(PWRCTL_POL)
PWRMGMT_EN#: R10.1 U2.40(FPMGT/SMBA1/SS_UP)
SSRXM_DN1: J2.5(SSRXN) U2.7(USB_SSRXM_DN1) U3.1(NC1) U3.14(D1+)
SSRXM_DN2: J3.5(SSRXN) U2.15(USB_SSRXM_DN2) U4.7(NC7) U4.8(D3-)
SSRXM_DN3: J4.5(SSRXN) U2.23(USB_SSRXM_DN3) U5.7(NC7) U5.8(D3-)
SSRXM_DN4: J5.5(SSRXN) U2.30(USB_SSRXM_DN4) U6.7(NC7) U6.8(D3-)
SSRXM_UP: J1.10(RX+) U1.1(NC1) U1.14(D1+) U2.59(USB_SSRXM_UP)
SSRXP_DN1: J2.6(SSRXP) U2.6(USB_SSRXP_DN1) U3.2(NC2) U3.13(D1-)
SSRXP_DN2: J3.6(SSRXP) U2.14(USB_SSRXP_DN2) U4.6(NC6) U4.9(D3+)
SSRXP_DN3: J4.6(SSRXP) U2.22(USB_SSRXP_DN3) U5.6(NC6) U5.9(D3+)
SSRXP_DN4: J5.6(SSRXP) U2.29(USB_SSRXP_DN4) U6.6(NC6) U6.9(D3+)
SSRXP_UP: J1.9(RX-) U1.2(NC2) U1.13(D1-) U2.58(USB_SSRXP_UP)
SSTXM_DN1: C21.2 U2.4(USB_SSTXM_DN1)
SSTXM_DN2: C24.2 U2.12(USB_SSTXM_DN2)
SSTXM_DN3: C27.2 U2.20(USB_SSTXM_DN3)
SSTXM_DN4: C30.2 U2.27(USB_SSTXM_DN4)
SSTXM_PUP: C2.1 J1.6(TX-) U1.4(NC4) U1.11(D2-)
SSTXM_UP: C3.2 U2.56(USB_SSTXM_UP)
SSTXP_DN1: C22.2 U2.3(USB_SSTXP_DN1)
SSTXP_DN2: C25.2 U2.11(USB_SSTXP_DN2)
SSTXP_DN3: C28.2 U2.19(USB_SSTXP_DN3)
SSTXP_DN4: C31.2 U2.26(USB_SSTXP_DN4)
SSTXP_PUP: C3.1 J1.7(TX+) U1.3(NC3) U1.12(D2+)
SSTXP_UP: C2.2 U2.55(USB_SSTXP_UP)
USB_R1: R7.1 U2.64(USB_R1)
USB_VBUS_UP: R6.2 R8.1 U2.48(USB_VBUS)
XI: C5.1 R3.2 U2.62(XI) Y1.2
XO: C4.1 R3.1 U2.61(XO) Y1.1
N15283: R21.2 U9.4(EN)
N15348: D1.2(CATHODE) L1.1 U9.1(SW)
N15491: R22.2 R23.1 U9.3(FB)
N16295: R24.2 U10.4(EN)
N16337: D2.2(CATHODE) L2.1 U10.1(SW)
N16409: R25.2 R26.1 U10.3(FB)
N16775579: D4.2(ANODE) R27.2
N16809594: R34.1 U12.16(ILIM_HI)
N16810447: R20.1 U13.16(ILIM_HI)
N16811536: R38.1 U12.15(ILIM_LO)
N16811977: R40.1 U13.15(ILIM_LO)

Not connected (* = marked no-connect by the designer): U2 49(TEST)* 60(NC)*; U7 7(NC)*

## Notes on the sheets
sheet 1
- TUSB8041 BLOCK DIAGRAM
- Page 7
- 5V
- VBUS_OUT_1
- TPS2003C
- VBUS_OUT_2
- Page 5
- VBUS_OUT_1
- Page 3 & 4
- PORT 1
- DOWNSTREAM
  PORT 1
- DOWNSTREAM
  PORT 2
- Page 2
- Page 5
- VBUS_OUT_2
- USB3.0
- UPSTREAM
  USB PORT
- TUSB8041
- VBUS_IN
- DOWNSTREAM
  PORT 3
- PORT 2
- Page 7
- 5V
- VBUS_OUT_3
- DOWNSTREAM
  PORT 4
- TPS2546
- Page 6
- VBUS_OUT_3
- PORT 3
- Page 8
- Page 8
- 5V_IN
- FET SWITCH AND REGULATORS
- DC JACK
- VBUS_IN
- 5V
- Page 7
- VBUS_OUT_4
- Page 6
- VBUS_OUT_4
- TPS2546
- PORT 4
sheet 2
- USB3.0 MICRO-B UPSTREAM CONNECTOR
- THESE CONNECTIONS ARE FOR FLOW
  THROUGH ROUTING
- KEEP ESD CLOSE TO CONNECTOR
- USB 3.0 MICRO B CONNECTOR
- INTENTIONALLY SWAPPED POLARITY
- KEEP CAPS CLOSE TO CONNECTOR
- INTENTIONALLY SWAPPED POLARITY
- MICRO B RECEPTACLE
- 1
- 5
- 6
- 10
- ROUTE THESE LINES ON THE TOP SIDE ONLY
- USB 2
- USB 3
sheet 3
- TUSB 4 PORT USB3.0 HUB
- UPSTREAM PORT
- SIGNAL
- DEFINATION
- DOWNSTREAM PORTS
- I2C_ENABLE
- HIGH=I2C ENABLED
- PWRMGMT_EN#
- LOW=PWR MANAGEMENT ENABLED
- PWRCTL_POL
- HIGH=ACTIVE HIGH POLARITY
- GANGED
- LOW=INDIVIDUAL PORT CONTROL
- AUTO_EN
- LOW=AUTO MODE ENABLED
sheet 4
- TUSB 4 PORT HUB POWER
sheet 5
- DOWNSTREAM USB PORTS 1&2
- THESE CONNECTIONS ARE FOR FLOW
  THROUGH ROUTING
- KEEP ESD CLOSE TO CONNECTOR
- PORT 1
- SINGLE USB 3.0 CONNECTOR
- KEEP CAPS CLOSE TO CONNECTOR
- KEEP ESD CLOSE TO CONNECTOR
- PORT 2
- SINGLE USB 3.0 CONNECTOR
- KEEP CAPS CLOSE TO CONNECTOR
sheet 6
- DOWNSTREAM USB PORTS 3&4
- THESE CONNECTIONS ARE FOR FLOW
  THROUGH ROUTING
- KEEP ESD CLOSE TO CONNECTOR
- PORT 3
- SINGLE USB 3.0 CONNECTOR
- KEEP CAPS CLOSE TO CONNECTOR
- KEEP ESD CLOSE TO CONNECTOR
- PORT 4
- SINGLE USB 3.0 CONNECTOR
- KEEP CAPS CLOSE TO CONNECTOR
sheet 7
- USB POWER DELIVERY
- PORTS 1 & 2
- ACTIVE HIGH ENABLE:
  8041 HAS INTERNAL PULL-DOWNS
  THESE RESISTORS ENABLE
  BATTERY CHARGING ON
  PORTS 1 AND 2
- FIXED CURRENT LIMIT OUTPUT OF 2A
- PORT 3
- PORTS 3 AND 4
- (CTL1/CTL2/CTL3/ILIM_SEL=1)
- UP-STREAM CONNECTED
- CDP MODE
  (1.5A)
- ILIM_HIGH = 1.5A
- UP-STREAM DISCONNECTED
- DCP_AUTO MODE
  (1.5A)
- (CTL2/CTL3=1,CTL1/ILIM_SEL=0)
- PORT 4
- ILIM_HIGH = 1.5A
sheet 8
- 3.3V @450mA
- 1.1V @ 800mA
- BOARD_5V LED
- MID-MOUNT POWER CONNECTOR
- Vf=2.1V@20mA
- GND IS THE ON STATE
- JACK_INSERT
- CONDITION
- GND
- NO POWER CUBE
- BOARD_5V = VBUS_IN
- CUI INC #PJ-068B-SMT
- 5V
- POWER CUBE
- BOARD_5V COMES FROM POWER CUBE
- VBUS IS DISCONNECTED FROM BOARD_5V
- 2.5MM (5A RATED)
- FOR REV B
- POWER CUBE (SL POWER)
  CENB1040A0503F01 - 2.5MM CENTER POSITIVE
